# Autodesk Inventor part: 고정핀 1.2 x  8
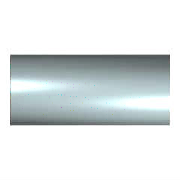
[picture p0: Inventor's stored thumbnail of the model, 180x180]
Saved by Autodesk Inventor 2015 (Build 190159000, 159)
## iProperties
IsCustomPart: 1
Created: 2012-02
Part Number: 고정핀 1.2 x  8
Material: 강철, 연강
Description: 평행 핀
Document SubType Name: Modeling
Standard: KS B 1320
Designer: P15F
Standards Organization: KS
Language: ko-KR
Size Designation: C 1.2 x  8
Categories: <MemberInstance><Categories><Category DisplayName="조임쇠" InternalName="e4da775c-781d-43d5-af7c-5136215cf5a6" Mnemonic="FSTN"><Category DisplayName="핀" InternalNa
Density: 1 g/cm^3
Appearance: 노란색
Author: P15F
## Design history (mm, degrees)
sketch "스케치1"
  geometry: C1 r 0.6 at (0, 0); 1 further point
  constraints: 1 centre point, 1 coincident
  dimensions: "d1" = 1.2 diameter of C1 (= NND)
extrude "본체" new body sketch "스케치1" distance "d2" = 8 (= NLG); taper "d3" = 0 deg
node "작업 평면1"
body "Solid1"
other parameters: "NND" = 1.2 [user parameter; used in 1 equation term], "NLG" = 8 [user parameter; used in 1 equation term], "d8" = 0, "d9" = 0, "d10" = 0
